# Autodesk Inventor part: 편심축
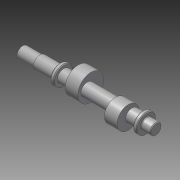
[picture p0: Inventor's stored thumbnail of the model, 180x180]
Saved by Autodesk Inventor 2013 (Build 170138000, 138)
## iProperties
Created: 2021-06
Part Number: 편심축
Material: 강철, 연강
Document SubType Name: Modeling
Designer: mdu-edu
Density: 7.86 g/cm^3
Author: mdu-edu
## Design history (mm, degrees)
sketch "스케치1"
  geometry: L1 (0, 0)-(180, 0); L2 (180, 0)-(180, -7.5); L3 (180, -7.5)-(167, -7.5); L4 (167, -7.5)-(167, -13); L5 (167, -13)-(162, -13); L6 (162, -13)-(162, -8.5); L7 (162, -8.5)-(56, -8.5); L8 (56, -8.5)-(56, -13); L9 (56, -13)-(51, -13); L10 (51, -13)-(51, -8.5); L11 (51, -8.5)-(24, -8.5); L12 (24, -8.5)-(24, -7.5); L13 (24, -7.5)-(0, -7.5); L14 (0, -7.5)-(0, 0)
  constraints: 28 end point, 6 parallel, 3 horizontal, 3 vertical, 1 collinear, 1 perpendicular
  dimensions: "d0" = 15 diameter of L13 L1; "d2" = 26 diameter of L9 L1; "d3" = 26 diameter of L5 L1; "d4" = 15 diameter of L3 L1; "d5" = 17 diameter of L7 L1; "d6" = 17 diameter of L11 L1; "d7" = 24 distance between parallel lines of L12 L14; "d8" = 51 distance between parallel lines of L14 L10; "d10" = 5 distance of L8.end L9.end; "d11" = 5 distance of L4.end L5.end; "d12" = 13 distance between parallel lines of L4 L2; "d13" = 180 distance between parallel lines of L14 L2
revolve "회전1" sketch "스케치1" stored, may be unused: angle "d14" = 90 deg
node "작업 평면1"
sketch "스케치2"
  geometry: C1 r 17.5 at (0, 5); 1 further point
  constraints: 1 centre point, 1 vertical alignment
  dimensions: "d16" = 35 diameter of C1; "d17" = 5 distance of C1.centre point (0, 0)
extrude "돌출1" join sketch "스케치2" distance "d18" = 17; taper "d19" = 0 deg
node "작업 평면2"
sketch "스케치3"
  geometry: C1 r 15 at (0, -5); 1 further point
  constraints: 1 centre point, 1 vertical alignment
  dimensions: "d21" = 30 diameter of C1; "d22" = 5 distance of point (0, 0) C1.centre
extrude "돌출2" join sketch "스케치3" distance "d23" = 17; taper "d24" = 0 deg
chamfer "모따기1" distance "d29" = 1; stored, may be unused: second distance "d30" = 2, angle "d31" = 45 deg
node "작업 평면3"
sketch "스케치4"
  geometry: L1 (-5.5, 2.5)-(12, 2.5); L2 (12, 2.5)-(12, -2.5); L3 (12, -2.5)-(-5.5, -2.5); L4 (12, 6.5)-(12, -6.5) reference; A1 r 2.5 centre (-5.5, 0) between (-5.5, 2.5) and (-5.5, -2.5); 1 further point
  constraints: 6 end point, 2 point on circle, 2 tangent, 1 centre point, 1 collinear, 1 horizontal, 1 horizontal alignment, 1 midpoint, 1 parallel, 1 perpendicular
  dimensions: "d25" = 5 diameter of A1; "d32" = 20 dimension on A1 L4
extrude "돌출3" cut sketch "스케치4" distance "d27" = 3; taper "d28" = 0 deg
fillet "모깎기1" dims "d33" = 0.6
fillet "모깎기2" dims "d34" = 1
node "솔리드1"
other parameters: "d15" = -70.5, "d20" = -32.5
